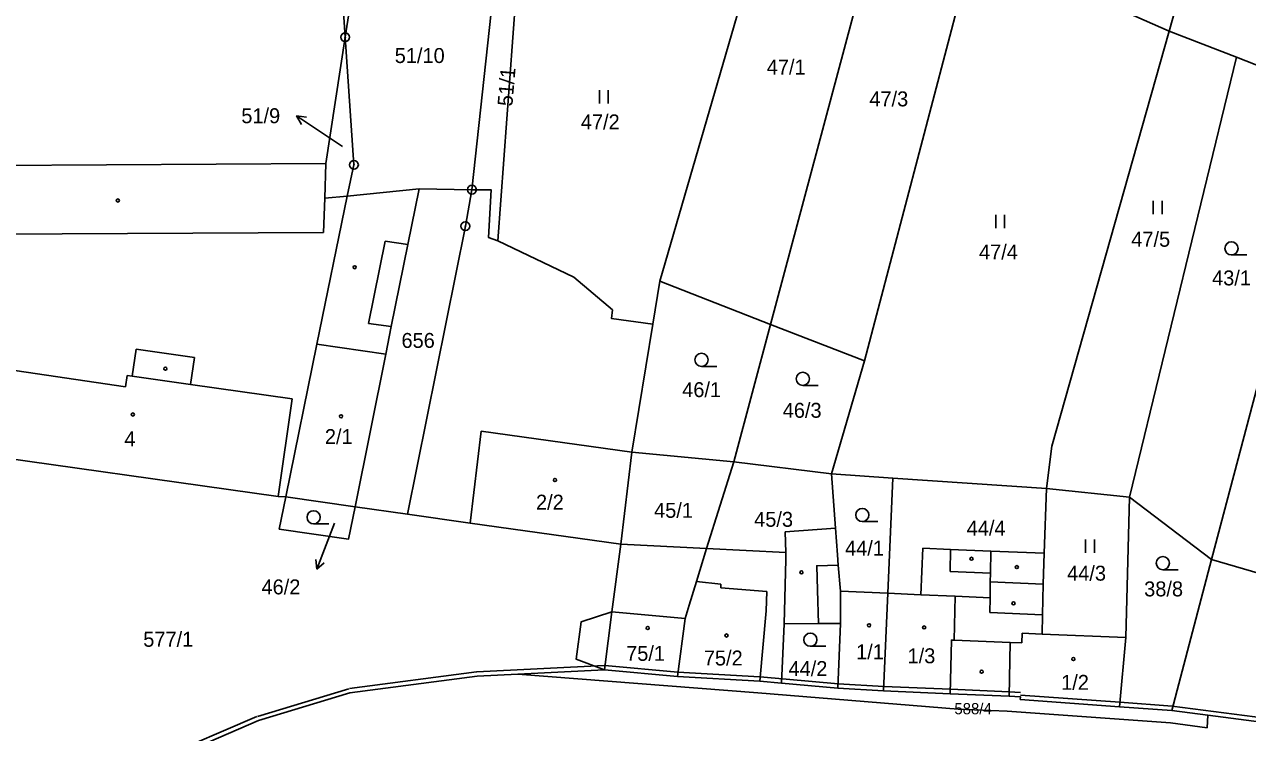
# Model space of a CAD drawing. Extents: x -783948 to -781889, y -1005870 to -1004430.
# Drawn here: x -782552.8 to -782413.6, y -1005431 to -1005350.5 of the extents above; entities that cross this region are included whole.
import ezdxf

# ---------------------------------------------------------------- set-up
doc = ezdxf.new("R2010")
doc.units = 0
for name, color, linetype in [('Vrstva 1', 7, 'Continuous'), ('Vrstva 2', 7, 'Continuous'), ('Vrstva 3', 7, 'Continuous'), ('Vrstva 4', 7, 'Continuous'), ('Vrstva 5', 7, 'Continuous'), ('Vrstva 7', 7, 'Continuous'), ('Vrstva 8', 7, 'Continuous')]:
    doc.layers.add(name, color=color, linetype=linetype)

msp = doc.modelspace()

# ---------------------------------------------------------------- linework, layer by layer
at = {"layer": 'Vrstva 1'}
for p, q in [((-782416.99, -1005330.99), (-782422.52, -1005351.21)), ((-782467.9, -1005384.57), (-782453.91, -1005332.25)), ((-782516.32, -1005351.91), (-782517.57, -1005333.81)), ((-782513.7, -1005334.83), (-782516.32, -1005351.91)), ((-782498.81, -1005340.92), (-782501.89, -1005369.25)), ((-782496.47, -1005341.55), (-782498.93, -1005375.08)), ((-782457.2, -1005388.74), (-782444.78, -1005341.39)), ((-782422.52, -1005351.21), (-782444.78, -1005341.39)), ((-782469.45, -1005341.63), (-782480.52, -1005379.66)), ((-782414.89, -1005354.18), (-782422.52, -1005351.21)), ((-782518.53, -1005366.29), (-782516.32, -1005351.91)), ((-782414.89, -1005354.18), (-782427.05, -1005404.23)), ((-782403.77, -1005358.5), (-782414.89, -1005354.18)), ((-782417.72, -1005411.34), (-782403.77, -1005358.5)), ((-782518.53, -1005366.29), (-782568.05, -1005366.58)), ((-782507.89, -1005369.17), (-782516.11, -1005369.98)), ((-782501.89, -1005369.25), (-782507.89, -1005369.17)), ((-782480.52, -1005379.66), (-782481.31, -1005384.55)), ((-782467.9, -1005384.57), (-782480.52, -1005379.66)), ((-782483.68, -1005399.13), (-782481.31, -1005384.55)), ((-782472.09, -1005400.23), (-782467.9, -1005384.57)), ((-782457.2, -1005388.74), (-782467.9, -1005384.57)), ((-782460.97, -1005401.57), (-782457.2, -1005388.74)), ((-782484.95, -1005409.57), (-782483.68, -1005399.13)), ((-782472.09, -1005400.23), (-782483.68, -1005399.13)), ((-782475.18, -1005410.06), (-782472.09, -1005400.23)), ((-782460.97, -1005401.57), (-782472.09, -1005400.23)), ((-782454, -1005402.08), (-782460.97, -1005401.57)), ((-782460.97, -1005401.57), (-782460.52, -1005407.74)), ((-782454.57, -1005415.17), (-782454, -1005402.08)), ((-782436.51, -1005403.23), (-782454, -1005402.08)), ((-782523.08, -1005404.21), (-782515.19, -1005405.35)), ((-782436.51, -1005403.23), (-782436.78, -1005410.62)), ((-782427.05, -1005404.23), (-782436.51, -1005403.23)), ((-782427.05, -1005404.23), (-782427.46, -1005420.21)), ((-782417.72, -1005411.34), (-782427.05, -1005404.23)), ((-782509.23, -1005406.18), (-782515.19, -1005405.35)), ((-782475.18, -1005410.06), (-782484.95, -1005409.57)), ((-782436.86, -1005414.12), (-782436.78, -1005410.62)), ((-782417.72, -1005411.34), (-782422.25, -1005428.49)), ((-782391.81, -1005418.85), (-782417.72, -1005411.34)), ((-782455.05, -1005426.26), (-782454.57, -1005415.17)), ((-782428.18, -1005428.07), (-782427.46, -1005420.21)), ((-782496.68, -1005424.37), (-782486.82, -1005423.88)), ((-782469.36, -1005426.49), (-782496.68, -1005424.37)), ((-782486.82, -1005423.88), (-782478.49, -1005424.63)), ((-782466.65, -1005425.4), (-782460.25, -1005425.97)), ((-782460.25, -1005425.97), (-782455.05, -1005426.26)), ((-782455.05, -1005426.26), (-782447.46, -1005426.59)), ((-782428.18, -1005428.07), (-782422.25, -1005428.49)), ((-782422.25, -1005428.49), (-782418.12, -1005429.03)), ((-782418.12, -1005429.03), (-782418.23, -1005430.46))]:
    msp.add_line(p, q, dxfattribs=at)
for points in [[(-782436.51, -1005403.23), (-782435.88, -1005398.43), (-782422.52, -1005351.21)], [(-782516.11, -1005369.98), (-782515.32, -1005366.42), (-782516.32, -1005351.91)], [(-782516.11, -1005369.98), (-782518.65, -1005370.23), (-782518.53, -1005366.29)], [(-782515.19, -1005405.35), (-782511.7, -1005387.95), (-782511.07, -1005384.83), (-782509.17, -1005375.48), (-782507.89, -1005369.17)], [(-782501.89, -1005369.25), (-782502.64, -1005373.4), (-782509.23, -1005406.18)], [(-782498.93, -1005375.08), (-782500.01, -1005374.68), (-782499.69, -1005369.28), (-782501.89, -1005369.25)], [(-782516.11, -1005369.98), (-782519.54, -1005386.82), (-782523.08, -1005404.21)], [(-782566.48, -1005372.13), (-782565.86, -1005374.34), (-782564.92, -1005377.62), (-782562.55, -1005386), (-782561.79, -1005388.68), (-782561.13, -1005398.91), (-782523.94, -1005404.17), (-782523.08, -1005404.21)], [(-782481.31, -1005384.55), (-782486.01, -1005383.9), (-782485.91, -1005382.93), (-782490.31, -1005379.19), (-782498.93, -1005375.08)], [(-782523.08, -1005404.21), (-782523.82, -1005407.87), (-782515.93, -1005409), (-782515.19, -1005405.35)], [(-782509.23, -1005406.18), (-782502.11, -1005407.18), (-782484.95, -1005409.57)], [(-782460.52, -1005407.74), (-782466.24, -1005408.18), (-782466.18, -1005410.51), (-782475.18, -1005410.06)], [(-782460.19, -1005411.96), (-782460.29, -1005410.8), (-782460.52, -1005407.74)], [(-782484.95, -1005409.57), (-782485.96, -1005417.29), (-782489.46, -1005418.43), (-782490.01, -1005422.67), (-782486.82, -1005423.88)], [(-782478.49, -1005424.63), (-782477.64, -1005418.04), (-782477.17, -1005416.53), (-782476.34, -1005413.82), (-782475.18, -1005410.06)], [(-782436.78, -1005410.62), (-782442.82, -1005410.37), (-782447.41, -1005410.18), (-782450.57, -1005410.05), (-782450.79, -1005415.33), (-782454.57, -1005415.17)], [(-782460.19, -1005411.96), (-782462.64, -1005412.03), (-782462.55, -1005414.81), (-782462.43, -1005418.62)], [(-782454.57, -1005415.17), (-782459.96, -1005414.93), (-782460.19, -1005411.96)], [(-782436.86, -1005414.12), (-782442.9, -1005413.87), (-782442.9, -1005415.67), (-782446.9, -1005415.5), (-782447.02, -1005420.5), (-782447.32, -1005420.49), (-782447.46, -1005426.59)], [(-782427.46, -1005420.21), (-782437, -1005419.8), (-782436.94, -1005417.62), (-782436.86, -1005414.12)], [(-782466.65, -1005425.4), (-782466.37, -1005418.66), (-782462.43, -1005418.62)], [(-782462.43, -1005418.62), (-782459.93, -1005418.6), (-782460.25, -1005425.97)], [(-782579.97, -1005495.74), (-782568.65, -1005477.69), (-782558.84, -1005458.5), (-782552.43, -1005447.81), (-782544.09, -1005439.4), (-782537.3, -1005434.44), (-782526.17, -1005429.65), (-782515.78, -1005426.51), (-782501.3, -1005424.6), (-782496.68, -1005424.37)], [(-782478.49, -1005424.63), (-782469.14, -1005425.18), (-782466.65, -1005425.4)], [(-782418.23, -1005430.46), (-782422.39, -1005429.91), (-782440.97, -1005428.56), (-782446.54, -1005428.36), (-782469.36, -1005426.49)], [(-782447.46, -1005426.59), (-782440.76, -1005426.88), (-782439.46, -1005426.94), (-782439.48, -1005427.24), (-782428.18, -1005428.07)], [(-782418.12, -1005429.03), (-782399.25, -1005431.5), (-782381.27, -1005432.53), (-782368.27, -1005428.25)]]:
    msp.add_lwpolyline(points, dxfattribs=at)
at = {"layer": 'Vrstva 3'}
for p, q in [((-782487.39, -1005359.43), (-782487.39, -1005357.93)), ((-782486.39, -1005359.43), (-782486.39, -1005357.93)), ((-782424.34, -1005372.03), (-782424.34, -1005370.53)), ((-782423.34, -1005372.03), (-782423.34, -1005370.53)), ((-782442.26, -1005373.62), (-782442.26, -1005372.12)), ((-782441.26, -1005373.62), (-782441.26, -1005372.12)), ((-782415.45, -1005376.68), (-782413.7, -1005376.68)), ((-782475.76, -1005389.36), (-782474.01, -1005389.36)), ((-782464.24, -1005391.52), (-782462.49, -1005391.52)), ((-782457.46, -1005407.01), (-782455.71, -1005407.01)), ((-782519.91, -1005407.27), (-782518.16, -1005407.27)), ((-782432.05, -1005410.55), (-782432.05, -1005409.05)), ((-782431.05, -1005410.55), (-782431.05, -1005409.05)), ((-782423.25, -1005412.48), (-782421.5, -1005412.48)), ((-782463.37, -1005421.2), (-782461.62, -1005421.2))]:
    msp.add_line(p, q, dxfattribs=at)
for centre in [(-782415.45, -1005375.93), (-782475.76, -1005388.61), (-782464.24, -1005390.77), (-782457.46, -1005406.26), (-782519.91, -1005406.52), (-782423.25, -1005411.73), (-782463.37, -1005420.45)]:
    msp.add_circle(centre, 0.75, dxfattribs=at)
at = {"layer": 'Vrstva 4'}
for p, q in [((-782518.77, -1005374.13), (-782518.65, -1005370.23)), ((-782565.86, -1005374.34), (-782518.77, -1005374.13)), ((-782513.65, -1005384.46), (-782511.75, -1005375.11)), ((-782511.75, -1005375.11), (-782509.17, -1005375.48)), ((-782513.65, -1005384.46), (-782511.07, -1005384.83)), ((-782540.55, -1005390.48), (-782540.12, -1005387.41)), ((-782540.12, -1005387.41), (-782533.48, -1005388.35)), ((-782519.54, -1005386.82), (-782511.7, -1005387.95)), ((-782561.79, -1005388.68), (-782541.32, -1005391.69)), ((-782533.91, -1005391.42), (-782533.48, -1005388.35)), ((-782541.32, -1005391.69), (-782541.14, -1005390.4)), ((-782541.14, -1005390.4), (-782540.55, -1005390.48)), ((-782540.55, -1005390.48), (-782533.91, -1005391.42)), ((-782533.91, -1005391.42), (-782522.37, -1005393.06)), ((-782523.94, -1005404.17), (-782522.37, -1005393.06)), ((-782502.11, -1005407.18), (-782500.84, -1005396.74)), ((-782500.84, -1005396.74), (-782483.68, -1005399.13)), ((-782466.16, -1005411.32), (-782466.18, -1005410.51)), ((-782447.47, -1005412.68), (-782447.41, -1005410.18)), ((-782442.88, -1005412.87), (-782442.82, -1005410.37)), ((-782466.37, -1005418.66), (-782466.16, -1005411.32)), ((-782473.55, -1005414.13), (-782476.34, -1005413.82)), ((-782442.88, -1005412.87), (-782447.47, -1005412.68)), ((-782442.9, -1005413.87), (-782442.88, -1005412.87)), ((-782473.57, -1005414.55), (-782473.55, -1005414.13)), ((-782468.34, -1005414.95), (-782473.57, -1005414.55)), ((-782468.4, -1005417.16), (-782468.34, -1005414.95)), ((-782459.93, -1005418.6), (-782459.96, -1005414.93)), ((-782450.79, -1005415.33), (-782446.9, -1005415.5)), ((-782442.94, -1005417.37), (-782442.9, -1005415.67)), ((-782486.82, -1005423.88), (-782485.96, -1005417.29)), ((-782485.96, -1005417.29), (-782477.64, -1005418.04)), ((-782469.14, -1005425.18), (-782468.4, -1005417.16)), ((-782442.94, -1005417.37), (-782436.94, -1005417.62)), ((-782447.02, -1005420.5), (-782440.62, -1005420.78)), ((-782440.62, -1005420.78), (-782440.76, -1005426.88)), ((-782440.62, -1005420.78), (-782439.3, -1005420.8)), ((-782439.25, -1005419.7), (-782439.3, -1005420.8)), ((-782439.25, -1005419.7), (-782437, -1005419.8)), ((-782501.32, -1005424.1), (-782486.84, -1005423.38)), ((-782486.77, -1005423.38), (-782478.44, -1005424.13)), ((-782515.84, -1005426.01), (-782501.36, -1005424.1)), ((-782469.11, -1005424.68), (-782478.46, -1005424.13)), ((-782469.1, -1005424.68), (-782460.21, -1005425.47)), ((-782526.31, -1005429.17), (-782515.92, -1005426.03)), ((-782455.02, -1005425.76), (-782460.22, -1005425.47)), ((-782455.03, -1005425.76), (-782447.44, -1005426.09)), ((-782447.44, -1005426.09), (-782440.74, -1005426.38)), ((-782439.44, -1005426.44), (-782440.74, -1005426.38)), ((-782439.44, -1005426.74), (-782428.14, -1005427.57)), ((-782428.14, -1005427.57), (-782422.21, -1005427.99)), ((-782537.5, -1005433.98), (-782526.37, -1005429.19)), ((-782422.18, -1005427.99), (-782399.18, -1005431))]:
    msp.add_line(p, q, dxfattribs=at)
at = {"layer": 'Vrstva 5'}
for centre in [(-782542.19, -1005370.48), (-782515.23, -1005378.07), (-782536.78, -1005389.62), (-782540.49, -1005394.83), (-782516.79, -1005395.03), (-782492.44, -1005402.28), (-782445.03, -1005411.24), (-782439.87, -1005412.19), (-782464.39, -1005412.79), (-782440.25, -1005416.31), (-782481.89, -1005419.12), (-782456.69, -1005418.81), (-782450.42, -1005419.05), (-782472.92, -1005419.97), (-782433.44, -1005422.65), (-782443.88, -1005424.09)]:
    msp.add_circle(centre, 0.175, dxfattribs=at)
at = {"layer": 'Vrstva 7'}
for p, q in [((-782519.35, -1005362.52), (-782521.84, -1005360.84)), ((-782521.84, -1005360.84), (-782520.73, -1005360.99)), ((-782521.84, -1005360.84), (-782521.29, -1005361.82)), ((-782516.63, -1005364.35), (-782519.35, -1005362.52)), ((-782517.53, -1005407.19), (-782518.47, -1005409.64)), ((-782518.47, -1005409.64), (-782519.55, -1005412.44)), ((-782519.55, -1005412.44), (-782519.65, -1005411.33)), ((-782519.55, -1005412.44), (-782518.72, -1005411.69))]:
    msp.add_line(p, q, dxfattribs=at)
at = {"layer": 'Vrstva 8'}
for centre, radius in [((-782516.32, -1005351.91), 0.5), ((-782516.32, -1005351.91), 0.0303), ((-782515.32, -1005366.42), 0.5), ((-782515.32, -1005366.42), 0.0303), ((-782501.89, -1005369.25), 0.5), ((-782501.89, -1005369.25), 0.0303), ((-782502.64, -1005373.4), 0.5), ((-782502.64, -1005373.4), 0.0303)]:
    msp.add_circle(centre, radius, dxfattribs=at)

# ---------------------------------------------------------------- texts
at = {"layer": 'Vrstva 2'}
for s, height, p in [('51/10', 1.7, (-782510.68, -1005354.84)), ('47/1', 1.7, (-782468.34, -1005356.15)), ('47/3', 1.7, (-782456.66, -1005359.77)), ('51/9', 1.7, (-782528.14, -1005361.69)), ('47/2', 1.7, (-782489.5, -1005362.39)), ('47/5', 1.7, (-782426.85, -1005375.74)), ('47/4', 1.7, (-782444.18, -1005377.19)), ('43/1', 1.7, (-782417.65, -1005380.14)), ('656', 1.7, (-782509.91, -1005387.25)), ('46/1', 1.7, (-782477.96, -1005392.85)), ('46/3', 1.7, (-782466.52, -1005395.2)), ('4', 1.7, (-782541.45, -1005398.44)), ('2/1', 1.7, (-782518.63, -1005398.19)), ('2/2', 1.7, (-782494.6, -1005405.65)), ('45/1', 1.7, (-782481.16, -1005406.58)), ('45/3', 1.7, (-782469.77, -1005407.6)), ('44/4', 1.7, (-782445.58, -1005408.6)), ('44/1', 1.7, (-782459.42, -1005410.88)), ('44/3', 1.7, (-782434.15, -1005413.73)), ('46/2', 1.7, (-782525.84, -1005415.29)), ('38/8', 1.7, (-782425.38, -1005415.52)), ('577/1', 1.7, (-782539.3, -1005421.25)), ('1/1', 1.7, (-782458.17, -1005422.67)), ('75/1', 1.7, (-782484.34, -1005422.85)), ('75/2', 1.7, (-782475.5, -1005423.38)), ('1/3', 1.7, (-782452.31, -1005423.13)), ('44/2', 1.7, (-782465.86, -1005424.58)), ('1/2', 1.7, (-782434.83, -1005426.15)), ('588/4', 1.271, (-782446.98, -1005428.93))]:
    msp.add_text(s, height=height, dxfattribs=at).set_placement(p)
msp.add_text('51/1', height=1.7, rotation=85, dxfattribs=at).set_placement((-782497.3, -1005359.81))

doc.saveas('drawing.dxf')
